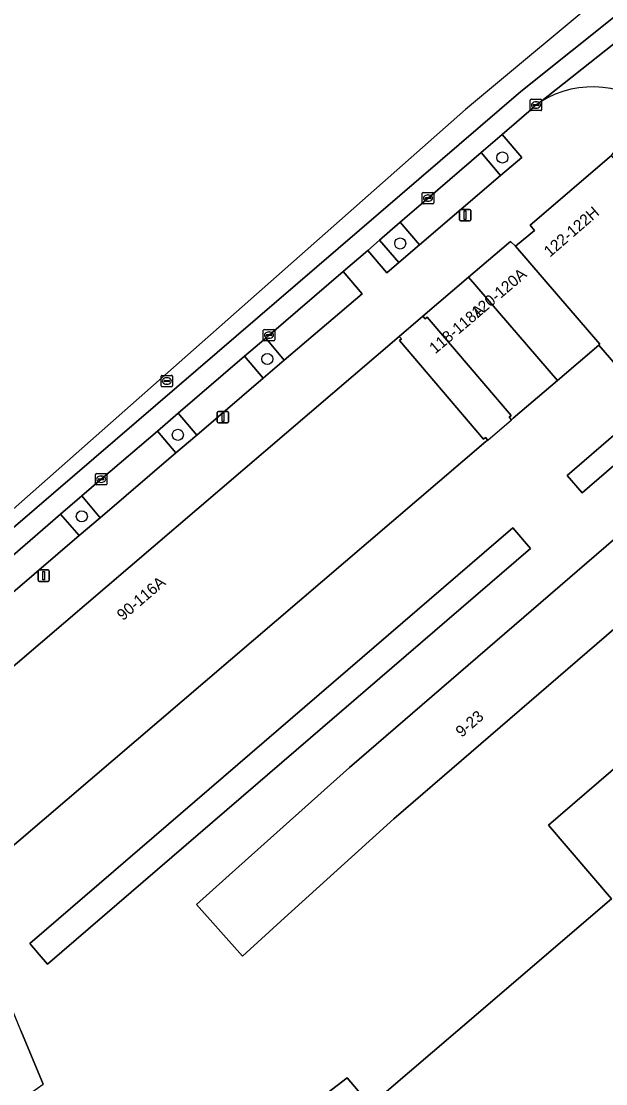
# Model space of a CAD drawing. Extents: x 162172 to 163187, y 382874 to 383685.
# Drawn here: x 162400 to 162451.5, y 383245.3 to 383338.9 of the extents above; entities that cross this region are included whole.
import ezdxf

# ---------------------------------------------------------------- set-up
doc = ezdxf.new("R2010")
doc.units = 0
for name, color, linetype in [('IMGEO_Boom', 7, 'Continuous'), ('IMGEO_Erf', 7, 'Continuous'), ('IMGEO_Kolk', 7, 'Continuous'), ('IMGEO_Lichtmast', 7, 'Continuous'), ('IMGEO_Pand', 7, 'Continuous'), ('IMGEO_Pand_nummerreeks', 7, 'Continuous'), ('IMGEO_Pand_overbouw', 7, 'Continuous'), ('IMGEO_Parkeervlak_open', 7, 'Continuous'), ('IMGEO_Rijbaan_lokaal_gesloten', 7, 'Continuous'), ('IMGEO_Rijbaan_lokaal_open', 7, 'Continuous'), ('IMGEO_Rioolput', 7, 'Continuous'), ('IMGEO_Verkeerseiland_groen', 7, 'Continuous'), ('IMGEO_Voetpad_open', 7, 'Continuous')]:
    doc.layers.add(name, color=color, linetype=linetype)

msp = doc.modelspace()

# ---------------------------------------------------------------- linework, layer by layer
at = {"layer": 'IMGEO_Boom'}
for centre in [(162442.443, 383326.893), (162433.434, 383319.32), (162421.72, 383309.149), (162413.837, 383302.461), (162405.373, 383295.285)]:
    msp.add_circle(centre, 0.489, dxfattribs=at)
at = {"layer": 'IMGEO_Erf'}
for points in [[(162456.742, 383303.654), (162449.457, 383297.368), (162448.144, 383298.889), (162455.43, 383305.175), (162450.944, 383310.374), (162447.296, 383307.261), (162443.396, 383303.932), (162443.227, 383303.788), (162443.032, 383304.016), (162443.2, 383304.159), (162435.797, 383312.829), (162435.629, 383312.686), (162435.434, 383312.914), (162433.35, 383311.136), (162433.545, 383310.908), (162433.377, 383310.765), (162440.782, 383302.095), (162440.949, 383302.237), (162441.144, 383302.009), (162440.977, 383301.867), (162393.697, 383261.491)], [(162415.492, 383261.098), (162419.215, 383264.437), (162428.95, 383273.168), (162453.92, 383294.688)], [(162457.563, 383289.917), (162432.862, 383268.63), (162423.228, 383259.906), (162419.521, 383256.549), (162415.492, 383261.098)], [(162432.032, 383244.453), (162438.509, 383250), (162452.05, 383261.596), (162446.489, 383268.073), (162453.052, 383273.709)], [(162399.993, 383250), (162401.954, 383245.27)], [(162407.685, 383229.67), (162428.769, 383245.828), (162438.517, 383234.328)]]:
    msp.add_lwpolyline(points, dxfattribs=at)
msp.add_lwpolyline([(162402.347, 383255.851), (162401.615, 383256.702), (162400.784, 383257.668), (162443.346, 383294.265), (162444.909, 383292.448)], close=True, dxfattribs=at)
at = {"layer": 'IMGEO_Kolk'}
for p, q in [((162444.896, 383331.095), (162444.896, 383331.947)), ((162444.971, 383332.021), (162445.823, 383332.021)), ((162445.384, 383331.801), (162445.409, 383331.801)), ((162445.897, 383331.947), (162445.897, 383331.095)), ((162445.823, 383331.021), (162444.971, 383331.021)), ((162445.155, 383331.515), (162445.155, 383331.527)), ((162445.593, 383331.478), (162445.195, 383331.478)), ((162445.198, 383331.564), (162445.596, 383331.564)), ((162445.407, 383331.241), (162445.382, 383331.241)), ((162445.639, 383331.527), (162445.639, 383331.515)), ((162435.382, 383322.888), (162435.382, 383323.74)), ((162435.457, 383323.814), (162436.309, 383323.814)), ((162435.641, 383323.308), (162435.641, 383323.32)), ((162436.079, 383323.271), (162435.681, 383323.271)), ((162435.684, 383323.357), (162436.082, 383323.357)), ((162435.87, 383323.594), (162435.895, 383323.594)), ((162436.125, 383323.32), (162436.125, 383323.308)), ((162436.383, 383323.74), (162436.383, 383322.888)), ((162436.309, 383322.814), (162435.457, 383322.814)), ((162435.893, 383323.034), (162435.868, 383323.034)), ((162421.37, 383310.82), (162421.37, 383311.672)), ((162421.445, 383311.746), (162422.297, 383311.746)), ((162421.629, 383311.24), (162421.629, 383311.252)), ((162422.067, 383311.203), (162421.669, 383311.203)), ((162421.672, 383311.289), (162422.07, 383311.289)), ((162421.858, 383311.526), (162421.883, 383311.526)), ((162422.113, 383311.252), (162422.113, 383311.24)), ((162422.371, 383311.672), (162422.371, 383310.82)), ((162422.297, 383310.746), (162421.445, 383310.746)), ((162421.881, 383310.966), (162421.856, 383310.966)), ((162406.581, 383298.131), (162406.581, 383298.983)), ((162406.656, 383299.057), (162407.508, 383299.057)), ((162407.582, 383298.983), (162407.582, 383298.131)), ((162407.508, 383298.057), (162406.656, 383298.057)), ((162406.84, 383298.551), (162406.84, 383298.563)), ((162407.278, 383298.514), (162406.88, 383298.514)), ((162406.883, 383298.6), (162407.281, 383298.6)), ((162407.092, 383298.277), (162407.067, 383298.277)), ((162407.069, 383298.837), (162407.094, 383298.837)), ((162407.324, 383298.563), (162407.324, 383298.551))]:
    msp.add_line(p, q, dxfattribs=at)
for points in [[(162444.896, 383331.095), (162444.896, 383331.947)], [(162444.971, 383332.021), (162445.823, 383332.021)], [(162445.897, 383331.947), (162445.897, 383331.095)], [(162445.823, 383331.021), (162444.971, 383331.021)], [(162435.382, 383322.888), (162435.382, 383323.74)], [(162435.457, 383323.814), (162436.309, 383323.814)], [(162436.383, 383323.74), (162436.383, 383322.888)], [(162436.309, 383322.814), (162435.457, 383322.814)], [(162421.37, 383310.82), (162421.37, 383311.672)], [(162421.445, 383311.746), (162422.297, 383311.746)], [(162422.371, 383311.672), (162422.371, 383310.82)], [(162422.297, 383310.746), (162421.445, 383310.746)], [(162406.581, 383298.131), (162406.581, 383298.983)], [(162406.656, 383299.057), (162407.508, 383299.057)], [(162407.582, 383298.983), (162407.582, 383298.131)], [(162407.508, 383298.057), (162406.656, 383298.057)]]:
    msp.add_lwpolyline(points, dxfattribs=at)
for centre, radius, start, end in [((162444.973, 383331.945), 0.0765, 91.55205, 178.44795), ((162444.973, 383331.945), 0.0765, 91.55205, 178.44795), ((162445.821, 383331.945), 0.0765, 1.55205, 88.44795), ((162445.821, 383331.945), 0.0765, 1.55205, 88.44795), ((162444.973, 383331.097), 0.0765, 181.55205, 268.44795), ((162444.973, 383331.097), 0.0765, 181.55205, 268.44795), ((162445.195, 383331.524), 0.0403, 85.87752, 175.75265), ((162445.192, 383331.514), 0.0366, 178.93798, 274.71019), ((162445.596, 383331.521), 0.043, 264.86636, 352.45326), ((162445.6, 383331.526), 0.0386, 1.73085, 96.63898), ((162445.821, 383331.097), 0.0765, 271.55205, 358.44795), ((162445.821, 383331.097), 0.0765, 271.55205, 358.44795), ((162435.459, 383323.738), 0.0765, 91.55205, 178.44795), ((162435.459, 383323.738), 0.0765, 91.55205, 178.44795), ((162435.681, 383323.317), 0.0403, 85.87752, 175.75265), ((162435.678, 383323.307), 0.0366, 178.93798, 274.71019), ((162436.082, 383323.314), 0.043, 264.86636, 352.45326), ((162436.086, 383323.319), 0.0386, 1.73085, 96.63898), ((162436.307, 383323.738), 0.0765, 1.55205, 88.44795), ((162436.307, 383323.738), 0.0765, 1.55205, 88.44795), ((162435.459, 383322.89), 0.0765, 181.55205, 268.44795), ((162435.459, 383322.89), 0.0765, 181.55205, 268.44795), ((162436.307, 383322.89), 0.0765, 271.55205, 358.44795), ((162436.307, 383322.89), 0.0765, 271.55205, 358.44795), ((162421.447, 383311.67), 0.0765, 91.55205, 178.44795), ((162421.447, 383311.67), 0.0765, 91.55205, 178.44795), ((162421.669, 383311.249), 0.0403, 85.87752, 175.75265), ((162421.666, 383311.239), 0.0366, 178.93798, 274.71019), ((162422.07, 383311.246), 0.043, 264.86636, 352.45326), ((162422.074, 383311.251), 0.0386, 1.73085, 96.63898), ((162422.295, 383311.67), 0.0765, 1.55205, 88.44795), ((162422.295, 383311.67), 0.0765, 1.55205, 88.44795), ((162421.447, 383310.822), 0.0765, 181.55205, 268.44795), ((162421.447, 383310.822), 0.0765, 181.55205, 268.44795), ((162422.295, 383310.822), 0.0765, 271.55205, 358.44795), ((162422.295, 383310.822), 0.0765, 271.55205, 358.44795), ((162406.658, 383298.981), 0.0765, 91.55205, 178.44795), ((162406.658, 383298.981), 0.0765, 91.55205, 178.44795), ((162407.506, 383298.981), 0.0765, 1.55205, 88.44795), ((162407.506, 383298.981), 0.0765, 1.55205, 88.44795), ((162406.658, 383298.133), 0.0765, 181.55205, 268.44795), ((162406.658, 383298.133), 0.0765, 181.55205, 268.44795), ((162406.88, 383298.56), 0.0403, 85.87752, 175.75265), ((162406.877, 383298.55), 0.0366, 178.93798, 274.71019), ((162407.281, 383298.557), 0.043, 264.86636, 352.45326), ((162407.285, 383298.562), 0.0386, 1.73085, 96.63898), ((162407.506, 383298.133), 0.0765, 271.55205, 358.44795), ((162407.506, 383298.133), 0.0765, 271.55205, 358.44795)]:
    msp.add_arc(centre, radius, start, end, dxfattribs=at)
for centre, major_axis, ratio, start_param, end_param in [((162445.383, 383331.521), (-0.387, 0.002), 0.722429, 4.712389, 7.853982), ((162445.408, 383331.521), (-0.39, 0.002), 0.717154, 1.570796, 4.712389), ((162435.869, 383323.314), (-0.387, 0.002), 0.722429, 4.712389, 7.853982), ((162435.894, 383323.314), (-0.39, 0.002), 0.717154, 1.570796, 4.712389), ((162421.857, 383311.246), (-0.387, 0.002), 0.722429, 4.712389, 7.853982), ((162421.882, 383311.246), (-0.39, 0.002), 0.717154, 1.570796, 4.712389), ((162407.068, 383298.557), (-0.387, 0.002), 0.722429, 4.712389, 7.853982), ((162407.093, 383298.557), (-0.39, 0.002), 0.717154, 1.570796, 4.712389)]:
    msp.add_ellipse(centre, major_axis=major_axis, ratio=ratio, start_param=start_param, end_param=end_param, dxfattribs=at)
at = {"layer": 'IMGEO_Lichtmast'}
for p, q in [((162438.76, 383322.313), (162439.55, 383322.313)), ((162439.55, 383322.313), (162438.76, 383322.313)), ((162438.66, 383321.413), (162438.66, 383322.213)), ((162438.66, 383322.213), (162438.66, 383321.413)), ((162439.65, 383322.213), (162439.65, 383321.413)), ((162439.65, 383321.413), (162439.65, 383322.213)), ((162439.55, 383321.313), (162438.76, 383321.313)), ((162438.76, 383321.313), (162439.55, 383321.313)), ((162417.414, 383304.523), (162418.204, 383304.523)), ((162418.204, 383304.523), (162417.414, 383304.523)), ((162417.314, 383303.623), (162417.314, 383304.423)), ((162417.314, 383304.423), (162417.314, 383303.623)), ((162418.304, 383304.423), (162418.304, 383303.623)), ((162418.304, 383303.623), (162418.304, 383304.423)), ((162418.204, 383303.523), (162417.414, 383303.523)), ((162417.414, 383303.523), (162418.204, 383303.523)), ((162401.616, 383290.559), (162402.406, 383290.559)), ((162402.406, 383290.559), (162401.616, 383290.559)), ((162401.516, 383289.659), (162401.516, 383290.459)), ((162401.516, 383290.459), (162401.516, 383289.659)), ((162402.406, 383289.559), (162401.616, 383289.559)), ((162401.616, 383289.559), (162402.406, 383289.559)), ((162402.506, 383290.459), (162402.506, 383289.659)), ((162402.506, 383289.659), (162402.506, 383290.459))]:
    msp.add_line(p, q, dxfattribs=at)
for points in [[(162439.08, 383322.188), (162439.23, 383322.188), (162439.23, 383321.438), (162439.08, 383321.438), (162439.08, 383322.188)], [(162417.734, 383304.398), (162417.884, 383304.398), (162417.884, 383303.648), (162417.734, 383303.648), (162417.734, 383304.398)], [(162401.936, 383290.434), (162402.086, 383290.434), (162402.086, 383289.684), (162401.936, 383289.684), (162401.936, 383290.434)]]:
    msp.add_lwpolyline(points, dxfattribs=at)
for centre, start, end in [((162438.76, 383322.213), 90, 180), ((162438.76, 383322.213), 90, 180), ((162439.55, 383322.213), 0, 90), ((162439.55, 383322.213), 360, 90), ((162438.76, 383321.413), 180, 270), ((162438.76, 383321.413), 180, 270), ((162439.55, 383321.413), 270, 0), ((162439.55, 383321.413), 270, 0), ((162417.414, 383304.423), 90, 180), ((162417.414, 383304.423), 90, 180), ((162418.204, 383304.423), 0, 90), ((162418.204, 383304.423), 360, 90), ((162417.414, 383303.623), 180, 270), ((162417.414, 383303.623), 180, 270), ((162418.204, 383303.623), 270, 0), ((162418.204, 383303.623), 270, 0), ((162401.616, 383290.459), 90, 180), ((162401.616, 383290.459), 90, 180), ((162402.406, 383290.459), 0, 90), ((162402.406, 383290.459), 360, 90), ((162401.616, 383289.659), 180, 270), ((162401.616, 383289.659), 180, 270), ((162402.406, 383289.659), 270, 0), ((162402.406, 383289.659), 270, 0)]:
    msp.add_arc(centre, 0.1, start, end, dxfattribs=at)
at = {"layer": 'IMGEO_Pand'}
for points in [[(162457.58, 383320.662), (162456.008, 383322.49), (162452.069, 383327.069), (162444.895, 383320.923), (162445.281, 383320.45), (162443.597, 383319.075), (162447.197, 383314.895), (162451.028, 383310.448), (162450.944, 383310.374), (162455.43, 383305.175), (162455.669, 383304.898), (162456.742, 383303.654), (162459.975, 383299.907), (162466.195, 383305.473), (162465.975, 383305.729), (162468.569, 383307.965)], [(162443.597, 383319.075), (162443.151, 383319.499), (162442.968, 383319.342), (162439.462, 383316.351), (162447.296, 383307.261), (162450.944, 383310.374), (162451.028, 383310.448), (162447.197, 383314.895)], [(162447.296, 383307.261), (162439.462, 383316.351), (162435.434, 383312.914), (162435.629, 383312.686), (162435.797, 383312.829), (162443.2, 383304.159), (162443.032, 383304.016), (162443.227, 383303.788), (162443.396, 383303.932)], [(162440.977, 383301.867), (162441.144, 383302.009), (162440.949, 383302.237), (162440.782, 383302.095), (162433.377, 383310.765), (162433.545, 383310.908), (162433.35, 383311.136), (162385.904, 383270.617), (162385.97, 383270.54), (162393.697, 383261.491)], [(162456.742, 383303.654), (162455.669, 383304.898), (162455.43, 383305.175), (162448.144, 383298.889), (162449.457, 383297.368)], [(162444.909, 383292.448), (162443.346, 383294.265), (162400.784, 383257.668), (162401.615, 383256.702), (162402.347, 383255.851)], [(162457.563, 383289.917), (162457.832, 383290.149), (162453.92, 383294.688), (162428.95, 383273.168), (162419.215, 383264.437), (162415.492, 383261.098), (162419.521, 383256.549), (162423.228, 383259.906), (162432.862, 383268.63)], [(162480.072, 383265.207), (162467.752, 383279.555), (162463.597, 383276.001), (162460.487, 383273.341), (162459.518, 383273.224), (162457.316, 383275.789), (162457.627, 383276.056), (162456.845, 383276.966), (162453.052, 383273.709), (162446.489, 383268.073), (162452.05, 383261.596), (162438.509, 383250), (162432.032, 383244.453), (162442.165, 383232.652), (162462.365, 383250)], [(162417.764, 383220.743), (162426.429, 383223.977), (162438.517, 383234.328), (162428.769, 383245.828), (162407.685, 383229.67), (162410.393, 383223.994), (162410.591, 383223.58), (162413.696, 383226.166)]]:
    msp.add_lwpolyline(points, close=True, dxfattribs=at)
at = {"layer": 'IMGEO_Pand_overbouw'}
msp.add_lwpolyline([(162435.434, 383312.914), (162433.35, 383311.136), (162433.545, 383310.908), (162433.377, 383310.765), (162440.782, 383302.095), (162440.949, 383302.237), (162441.144, 383302.009), (162443.227, 383303.788), (162443.032, 383304.016), (162443.2, 383304.159), (162435.797, 383312.829), (162435.629, 383312.686)], close=True, dxfattribs=at)
at = {"layer": 'IMGEO_Parkeervlak_open'}
for points in [[(162435.134, 383319.199), (162442.286, 383325.317), (162440.561, 383327.336), (162435.884, 383323.314), (162433.438, 383321.191)], [(162421.577, 383310.994), (162423.217, 383309.03), (162430.075, 383314.882), (162428.402, 383316.843), (162421.871, 383311.247)], [(162419.703, 383309.383), (162413.876, 383304.375), (162415.499, 383302.445), (162421.353, 383307.446)], [(162405.385, 383297.095), (162406.978, 383295.162), (162413.657, 383300.868), (162412.03, 383302.794), (162407.084, 383298.557)], [(162397.674, 383290.459), (162399.284, 383288.577), (162405.135, 383293.59), (162403.505, 383295.477)]]:
    msp.add_lwpolyline(points, close=True, dxfattribs=at)
at = {"layer": 'IMGEO_Rijbaan_lokaal_gesloten'}
for points in [[(162241.995, 383156.412), (162244.53, 383159.301), (162248.008, 383164.875), (162250.915, 383168.143), (162371.03, 383269.104), (162392.188, 383288.18), (162444.061, 383332.714), (162462.172, 383347.171), (162500.099, 383379.33), (162504.312, 383382.919), (162503.092, 383384.494), (162452.553, 383342.284), (162439.186, 383331.12), (162372.302, 383272.085), (162334.992, 383240.797), (162331.864, 383238.174), (162267.807, 383184.457), (162185.082, 383115.085), (162181.627, 383109.075), (162174.82, 383097.237)], [(162445.777, 383331.778), (162464.553, 383346.647), (162467.025, 383348.679), (162472.339, 383353.202), (162490.914, 383369.044), (162496.178, 383373.597), (162505.769, 383381.038), (162504.312, 383382.919), (162500.099, 383379.33), (162462.172, 383347.171), (162444.061, 383332.714), (162392.188, 383288.18), (162371.03, 383269.104), (162250.915, 383168.143), (162248.008, 383164.875), (162244.53, 383159.301), (162241.995, 383156.412)], [(162382.591, 383277.584), (162383.627, 383278.47), (162385.49, 383280.064), (162391.521, 383285.223), (162393.446, 383286.861), (162395.665, 383288.75), (162397.674, 383290.459), (162403.505, 383295.477), (162405.385, 383297.095), (162407.084, 383298.557), (162412.03, 383302.794), (162413.876, 383304.375), (162419.703, 383309.383), (162421.577, 383310.994), (162421.871, 383311.247), (162428.402, 383316.843), (162430.571, 383318.702), (162431.619, 383319.611), (162433.438, 383321.191), (162435.884, 383323.314), (162440.561, 383327.336), (162442.406, 383328.911), (162443.681, 383330), (162445.202, 383331.321)]]:
    msp.add_lwpolyline(points, dxfattribs=at)
msp.add_arc((162450.001, 383325.873), 7.261, 125.57781, 131.37632, dxfattribs=at)
at = {"layer": 'IMGEO_Rijbaan_lokaal_open'}
for points in [[(162464.553, 383346.647), (162445.777, 383331.778)], [(162400.458, 383244.217), (162401.954, 383245.27), (162399.993, 383250), (162397.916, 383255.011), (162396.159, 383254.208), (162393.364, 383260.33), (162394.025, 383260.635)]]:
    msp.add_lwpolyline(points, dxfattribs=at)
msp.add_arc((162450.366, 383324.591), 8.527, 44.98531, 122.55818, dxfattribs=at)
at = {"layer": 'IMGEO_Rioolput'}
for p, q in [((162412.363, 383306.78), (162412.363, 383307.632)), ((162412.438, 383307.706), (162413.29, 383307.706)), ((162412.851, 383307.486), (162412.876, 383307.486)), ((162413.364, 383307.632), (162413.364, 383306.78)), ((162413.29, 383306.706), (162412.438, 383306.706)), ((162412.622, 383307.2), (162412.622, 383307.212)), ((162413.06, 383307.163), (162412.662, 383307.163)), ((162412.665, 383307.249), (162413.063, 383307.249)), ((162412.874, 383306.926), (162412.849, 383306.926)), ((162413.106, 383307.212), (162413.106, 383307.2))]:
    msp.add_line(p, q, dxfattribs=at)
for points in [[(162412.363, 383306.78), (162412.363, 383307.632)], [(162412.438, 383307.706), (162413.29, 383307.706)], [(162413.364, 383307.632), (162413.364, 383306.78)], [(162413.29, 383306.706), (162412.438, 383306.706)]]:
    msp.add_lwpolyline(points, dxfattribs=at)
for centre, radius, start, end in [((162412.44, 383307.63), 0.0765, 91.55205, 178.44795), ((162412.44, 383307.63), 0.0765, 91.55205, 178.44795), ((162413.288, 383307.63), 0.0765, 1.55205, 88.44795), ((162413.288, 383307.63), 0.0765, 1.55205, 88.44795), ((162412.44, 383306.782), 0.0765, 181.55205, 268.44795), ((162412.44, 383306.782), 0.0765, 181.55205, 268.44795), ((162412.662, 383307.209), 0.0403, 85.87752, 175.75265), ((162412.659, 383307.199), 0.0366, 178.93798, 274.71019), ((162413.063, 383307.206), 0.043, 264.86636, 352.45326), ((162413.067, 383307.211), 0.0386, 1.73085, 96.63898), ((162413.288, 383306.782), 0.0765, 271.55205, 358.44795), ((162413.288, 383306.782), 0.0765, 271.55205, 358.44795)]:
    msp.add_arc(centre, radius, start, end, dxfattribs=at)
for centre, major_axis, ratio, start_param, end_param in [((162412.85, 383307.206), (-0.387, 0.002), 0.722429, 4.712389, 7.853982), ((162412.875, 383307.206), (-0.39, 0.002), 0.717154, 1.570796, 4.712389)]:
    msp.add_ellipse(centre, major_axis=major_axis, ratio=ratio, start_param=start_param, end_param=end_param, dxfattribs=at)
at = {"layer": 'IMGEO_Verkeerseiland_groen'}
for points in [[(162442.406, 383328.911), (162440.561, 383327.336), (162442.286, 383325.317), (162444.144, 383326.908)], [(162433.438, 383321.191), (162431.619, 383319.611), (162433.304, 383317.641), (162435.134, 383319.199)], [(162421.577, 383310.994), (162419.703, 383309.383), (162421.353, 383307.446), (162423.217, 383309.03)], [(162413.876, 383304.375), (162412.03, 383302.794), (162413.657, 383300.868), (162415.499, 383302.445)], [(162405.385, 383297.095), (162403.505, 383295.477), (162405.135, 383293.59), (162406.978, 383295.162)]]:
    msp.add_lwpolyline(points, close=True, dxfattribs=at)
at = {"layer": 'IMGEO_Voetpad_open'}
for points in [[(162445.202, 383331.321), (162443.681, 383330), (162442.406, 383328.911), (162444.144, 383326.908), (162442.286, 383325.317), (162435.134, 383319.199), (162433.304, 383317.641), (162432.26, 383316.743), (162430.571, 383318.702), (162428.402, 383316.843), (162430.075, 383314.882), (162423.217, 383309.03), (162421.353, 383307.446), (162415.499, 383302.445), (162413.657, 383300.868), (162406.978, 383295.162), (162405.135, 383293.59), (162399.284, 383288.577)], [(162433.35, 383311.136), (162435.434, 383312.914), (162439.462, 383316.351), (162442.968, 383319.342), (162443.151, 383319.499), (162443.597, 383319.075), (162445.281, 383320.45), (162444.895, 383320.923), (162452.069, 383327.069), (162452.706, 383327.963), (162454.368, 383329.278), (162456.397, 383330.619)], [(162382.311, 383274.742), (162383.272, 383273.638), (162385.904, 383270.617), (162433.35, 383311.136)]]:
    msp.add_lwpolyline(points, dxfattribs=at)
msp.add_lwpolyline([(162433.304, 383317.641), (162431.619, 383319.611), (162430.571, 383318.702), (162432.26, 383316.743)], close=True, dxfattribs=at)
for centre, radius, start, end in [((162450.366, 383324.591), 8.527, 44.98531, 122.55818), ((162450.001, 383325.873), 7.261, 125.57781, 131.37632)]:
    msp.add_arc(centre, radius, start, end, dxfattribs=at)

# ---------------------------------------------------------------- texts
at = {"layer": 'IMGEO_Pand_nummerreeks'}
for s, rotation, p in [('122-122H', 40.9321, (162446.626, 383318.067)), ('120-120A', 40.37343, (162440.248, 383312.71)), ('118-118A', 40.18645, (162436.517, 383309.547)), ('90-116A', 40.45784, (162408.992, 383286.048)), ('9-23', 40.75449, (162438.851, 383275.77))]:
    msp.add_text(s, height=1, rotation=rotation, dxfattribs=at).set_placement(p)

doc.saveas('drawing.dxf')
